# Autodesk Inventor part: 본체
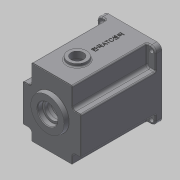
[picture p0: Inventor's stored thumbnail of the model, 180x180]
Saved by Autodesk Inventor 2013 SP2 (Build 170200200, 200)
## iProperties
Created: 2016-02
Part Number: 본체
Material: 일반
Document SubType Name: Modeling
Designer: mduedu
Density: 1 g/cm^3
Author: mduedu
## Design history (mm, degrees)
sketch "스케치1"
  geometry: L1 (-47, -47)-(47, -47); L2 (47, -47)-(47, 63); L3 (47, 63)-(-47, 63); L4 (-47, 63)-(-47, -47); 2 further points
  constraints: 8 end point, 2 parallel, 1 horizontal, 1 midpoint, 1 perpendicular, 1 vertical alignment
  dimensions: "d0" = 94 distance of L2.end L3.end; "d155" = 110 distance of L1.end L2.end; "d156" = 47 distance from line of L1 point (0, 0)
extrude "돌출1" new body sketch "스케치1" distance "d2" = 130; taper "d3" = 0 deg
sketch "스케치3"
  geometry: C1 r 40 at (0, 0); 1 further point
  constraints: 1 centre point, 1 coincident
  dimensions: "d9" = 80 diameter of C1
extrude "돌출3" cut sketch "스케치3" distance "d11" = 121; taper "d12" = 0 deg
sketch "스케치4"
  geometry: C1 r 21 at (0, 11); 1 further point
  constraints: 1 centre point, 1 vertical alignment
  dimensions: "d13" = 21 radius of C1; "d15" = 11 distance of point (0, 0) C1.centre
extrude "돌출4" join sketch "스케치4" distance "d16" = 7; taper "d17" = 0 deg
sketch "스케치5"
  geometry: C1 r 15 at (0, -20); 1 further point
  constraints: 1 centre point, 1 vertical alignment
  dimensions: "d18" = 15 radius of C1; "d20" = 20 distance of point (0, 0) C1.centre
extrude "돌출5" join sketch "스케치5" distance "d21" = 7; taper "d22" = 0 deg
sketch "스케치6"
  geometry: C1 r 28 at (0, 11); A1 r 21 centre (0, 11) between (8.978, -7.984) and (-8.978, -7.984) reference; 1 further point
  constraints: 1 centre point, 1 coincident
  dimensions: "d23" = 56 diameter of C1
extrude "돌출6" join sketch "스케치6" distance "d25" = 7; taper "d26" = -10 deg
hole "구멍1" diameter "d29" = 35; stored, may be unused: countersink angle "d33" = 90 deg, drill point angle "d35" = 0 deg; dims "d27" = 10, "d28" = 10, "d30" = 6, "d31" = 4, "d32" = 2, "d34" = 10
hole "구멍2" diameter "d38" = 22; stored, may be unused: countersink angle "d42" = 90 deg, drill point angle "d44" = 0 deg; dims "d36" = 10, "d37" = 10, "d39" = 6, "d40" = 4, "d41" = 2, "d43" = 7
hole "구멍3" diameter "d47" = 19; stored, may be unused: countersink angle "d51" = 90 deg, drill point angle "d53" = 0 deg; dims "d45" = 10, "d46" = 10, "d48" = 6, "d49" = 4, "d50" = 2, "d52" = 1
hole "구멍4" diameter "d56" = 32; stored, may be unused: countersink angle "d60" = 90 deg, drill point angle "d62" = 0 deg; dims "d54" = 10, "d55" = 10, "d57" = 6, "d58" = 4, "d59" = 2, "d61" = 8
hole "구멍5" diameter "d65" = 25; stored, may be unused: countersink angle "d69" = 90 deg, drill point angle "d71" = 0 deg; dims "d63" = 10, "d64" = 10, "d66" = 6, "d67" = 4, "d68" = 2, "d70" = 8
fillet "모깎기2" dims "d73" = 0.3
fillet "모깎기3" dims "d74" = 2
chamfer "모따기1" distance "d75" = 1; stored, may be unused: second distance "d76" = 2, angle "d77" = 45 deg
fillet "모깎기4" dims "d78" = 3
sketch "스케치16"
  geometry: L1 (-23, 32.726)-(23, 32.726); L2 (23, 32.726)-(23, 53); L3 (23, 53)-(-23, 53); L4 (-23, 53)-(-23, 32.726); L5 (-47, 63)-(47, 63) reference; 3 further points
  constraints: 8 end point, 2 parallel, 1 horizontal, 1 midpoint, 1 perpendicular, 1 vertical alignment, 2 other
  dimensions: "d160" = 46 distance of L2.end L3.end; "d163" = 10 distance between parallel lines of L3 L5
extrude "돌출15" cut sketch "스케치16" stored distance "d164" = 10; taper "d165" = 0 deg
fillet "모깎기5" dims "d79" = 2
fillet "모깎기15" dims "d166" = 5
sketch "스케치7"
  geometry: L1 (-23, 48)-(-23, 35.228) reference; L2 (23, 35.228)-(23, 48) reference; L3 (18, 53)-(-18, 53) reference; L4 (47, 63)-(47, -47) reference; L5 (47, -47)-(-47, -47) reference; L6 (-47, -47)-(-47, 63) reference; L7 (-47, 63)-(47, 63) reference; L8 (-26, 48)-(-26, 35.228); L9 (26, 35.228)-(26, 48); L10 (18, 56)-(-18, 56); C1 r 43 at (0, 0); A1 r 5 centre (-18, 48) between (-18, 53) and (-23, 48) reference; A2 r 5 centre (-28, 35.228) between (-24.889, 31.314) and (-23, 35.228) reference; A3 r 40 centre (0, 0) between (-24.889, 31.314) and (24.889, 31.314) reference; A4 r 5 centre (28, 35.228) between (23, 35.228) and (24.889, 31.314) reference; A5 r 5 centre (18, 48) between (23, 48) and (18, 53) reference; A6 r 8 centre (-18, 48) between (-18, 56) and (-26, 48); A7 r 2 centre (-28, 35.228) between (-26.756, 33.662) and (-26, 35.228); A8 r 43 centre (0, 0) between (-26.756, 33.662) and (26.756, 33.662); A9 r 2 centre (28, 35.228) between (26, 35.228) and (26.756, 33.662); A10 r 8 centre (18, 48) between (26, 48) and (18, 56); 1 further point
  constraints: 10 point on circle, 6 centre point, 6 end point, 1 coincident, 7 other
  dimensions: "d80" = 86 diameter of C1; "d167" = 3 distance between parallel lines of L3 L10
extrude "돌출7" cut sketch "스케치7" distance "d83" = 9; taper "d84" = 0 deg
sketch "스케치8" dims "d168" = 36
  geometry: L1 (-36, 4)-(-39.799, 4); L2 (-36, -4)-(-39.799, -4); A1 r 4 centre (-36, 0) between (-36, 4) and (-36, -4); A2 r 40 centre (0, 0) between (-24.889, 31.314) and (24.889, 31.314) reference; A3 r 40 centre (0, 0) between (-39.799, 4) and (-39.799, -4); 2 further points
  constraints: 5 point on circle, 4 end point, 2 centre point, 2 coincident, 2 horizontal alignment, 2 tangent, 1 horizontal, 1 parallel, 2 other
  dimensions: "d169" = 4 radius of A1
extrude "돌출9" join sketch "스케치8" stored distance "d89" = 9; taper "d90" = 0 deg
fillet "모깎기6" dims "d91" = 3.5
sketch "스케치9"
  geometry: L1 (47, 63)-(-47, 63) reference; L2 (47, -47)-(47, 63) reference; L3 (47, 63)-(33, 63); L4 (33, 63)-(33, 30); L5 (33, 30)-(47, 30); L6 (47, 30)-(47, 63); 2 further points
  constraints: 8 end point, 2 parallel, 1 horizontal, 1 perpendicular
  dimensions: "d95" = 33 distance from line of L4 point (0, 0); "d96" = 30 distance from line of L5 point (0, 0)
extrude "돌출10" cut sketch "스케치9" distance "d97" = 120; taper "d98" = 0 deg
sketch "스케치11"
  geometry: L1 (-40, -40)-(40, -40); L2 (40, -40)-(40, 56); L3 (40, 56)-(-40, 56); L4 (-40, 56)-(-40, -40); L5 (-47, -47)-(47, -47) reference; L6 (47, 63)-(-47, 63) reference; L7 (-47, 63)-(-47, -47) reference; C1 r 3.5 at (-40, 56); C2 r 3.5 at (40, 56); C3 r 3.5 at (40, -40); C4 r 3.5 at (-40, -40); 1 further point
  constraints: 8 end point, 4 centre point, 4 coincident, 3 equal radius, 2 parallel, 1 horizontal, 1 perpendicular
  dimensions: "d109" = 80 distance of L2.end L3.end; "d112" = 7 diameter of C1; "d157" = 7 distance from line of L1.start L5; "d158" = 7 distance between parallel lines of L6 L3; "d159" = 7 distance from line of L7 L3.end
extrude "돌출12" cut sketch "스케치11" stored distance "d113" = 63; taper "d114" = 0 deg
fillet "모깎기7" dims "d115" = 8
fillet "모깎기8" dims "d116" = 5
fillet "모깎기11" dims "d119" = 2
fillet "모깎기12" dims "d120" = 2
fillet "모깎기13" dims "d121" = 2
sketch "스케치12"
  geometry: 3 further points
  constraints: 2 horizontal alignment
hole "구멍6" sketch "스케치12" at (36, 0), (-36, 0) diameter "d122" = 3.242; stored, may be unused: countersink angle "d126" = 90 deg, drill point angle "d128" = 120 deg; dims "d123" = 7, "d124" = 4, "d125" = 2, "d127" = 9
sketch "스케치13"
  geometry: L1 (-33, 35)-(-33, 61) reference; L2 (-31, 63)-(31, 63) reference; L3 (33, 61)-(33, 35) reference; L4 (33, -35)-(33, -45) reference; L5 (31, -47)-(-31, -47) reference; L6 (-33, -45)-(-33, -35) reference; L7 (38, 30)-(45, 30) reference; L8 (47, 28)-(47, -28) reference; L9 (45, -30)-(38, -30) reference; L10 (-38, -30)-(-45, -30) reference; L11 (-47, -28)-(-47, 28) reference; L12 (-45, 30)-(-38, 30) reference; L13 (31, 62)-(-31, 62); L14 (-32, 61)-(-32, 35); L15 (-38, 29)-(-45, 29); L16 (-46, 28)-(-46, -28); L17 (-45, -29)-(-38, -29); L18 (-32, -35)-(-32, -45); L19 (-31, -46)-(31, -46); L20 (32, -45)-(32, -35); L21 (38, -29)-(45, -29); L22 (46, -28)-(46, 28); L23 (45, 29)-(38, 29); L24 (32, 35)-(32, 61); L25 (38, 30)-(45, 30) reference; L26 (47, 28)-(47, -28) reference; L27 (45, -30)-(38, -30) reference; L28 (33, -35)-(33, -45) reference; L29 (31, -47)-(-31, -47) reference; L30 (-33, -45)-(-33, -35) reference; L31 (-38, -30)-(-45, -30) reference; L32 (-47, -28)-(-47, 28) reference; L33 (-45, 30)-(-38, 30) reference; L34 (-33, 35)-(-33, 61) reference; L35 (33, 61)-(33, 35) reference; L36 (-31, 63)-(31, 63) reference; C1 r 16 at (0, 11) reference; C2 r 28 at (0, 11) reference; C3 r 16 at (0, 11) reference; C4 r 28 at (0, 11) reference; A1 r 5 centre (-38, 35) between (-38, 30) and (-33, 35) reference; A2 r 2 centre (-31, 61) between (-31, 63) and (-33, 61) reference; A3 r 2 centre (31, 61) between (33, 61) and (31, 63) reference; A4 r 5 centre (38, 35) between (33, 35) and (38, 30) reference; A5 r 5 centre (38, -35) between (38, -30) and (33, -35) reference; A6 r 2 centre (31, -45) between (31, -47) and (33, -45) reference; A7 r 2 centre (-31, -45) between (-33, -45) and (-31, -47) reference; A8 r 5 centre (-38, -35) between (-33, -35) and (-38, -30) reference; A9 r 2 centre (45, 28) between (47, 28) and (45, 30) reference; A10 r 2 centre (45, -28) between (45, -30) and (47, -28) reference; A11 r 2 centre (-45, -28) between (-47, -28) and (-45, -30) reference; A12 r 2 centre (-45, 28) between (-45, 30) and (-47, 28) reference; A13 r 1 centre (-31, 61) between (-31, 62) and (-32, 61); A14 r 6 centre (-38, 35) between (-38, 29) and (-32, 35); A15 r 1 centre (-45, 28) between (-45, 29) and (-46, 28); A16 r 1 centre (-45, -28) between (-46, -28) and (-45, -29); A17 r 6 centre (-38, -35) between (-32, -35) and (-38, -29); A18 r 1 centre (-31, -45) between (-32, -45) and (-31, -46); A19 r 1 centre (31, -45) between (31, -46) and (32, -45); A20 r 6 centre (38, -35) between (38, -29) and (32, -35); A21 r 1 centre (45, -28) between (45, -29) and (46, -28); A22 r 1 centre (45, 28) between (46, 28) and (45, 29); A23 r 6 centre (38, 35) between (32, 35) and (38, 29); A24 r 1 centre (31, 61) between (32, 61) and (31, 62); A25 r 5 centre (38, 35) between (33, 35) and (38, 30) reference; A26 r 2 centre (45, 28) between (47, 28) and (45, 30) reference; A27 r 2 centre (45, -28) between (45, -30) and (47, -28) reference; A28 r 5 centre (38, -35) between (38, -30) and (33, -35) reference; A29 r 2 centre (31, -45) between (31, -47) and (33, -45) reference; A30 r 2 centre (-31, -45) between (-33, -45) and (-31, -47) reference; A31 r 5 centre (-38, -35) between (-33, -35) and (-38, -30) reference; A32 r 2 centre (-45, -28) between (-47, -28) and (-45, -30) reference; A33 r 2 centre (-45, 28) between (-45, 30) and (-47, 28) reference; A34 r 5 centre (-38, 35) between (-38, 30) and (-33, 35) reference; A35 r 2 centre (-31, 61) between (-31, 63) and (-33, 61) reference; A36 r 2 centre (31, 61) between (33, 61) and (31, 63) reference
  constraints: 24 end point, 24 point on circle, 12 centre point, 23 other
  dimensions: "d154" = 1 distance between parallel lines of L13 L2
extrude "돌출13" cut sketch "스케치13" distance "d130" = 1; taper "d131" = 0 deg
fillet "모깎기14" dims "d147" = 0.3
sketch "스케치15"
  geometry: L1 (78, 0)-(0, 0) reference; 3 further points
  constraints: 1 midpoint, 1 vertical alignment, 1 other
  dimensions: "d148" = 40 distance of point (39, -40) point (39, 0)
feature "엠보싱1" sketch "스케치15" dims "d22" = 0, "d149" = 0.5, "d150" = 0
chamfer "모따기4" distance "d151" = 1; stored, may be unused: second distance "d152" = 2, angle "d153" = 45 deg
sketch "스케치17"
  geometry: L1 (39.004, -17.213)-(39.004, -18.809) reference; L2 (39.004, -18.809)-(38.548, -18.809) reference; L3 (38.548, -18.809)-(38.548, -17.213) reference; L4 (38.548, -17.213)-(35.455, -17.213) reference; L5 (35.455, -17.213)-(35.455, -16.822) reference; L6 (35.772, -16.659)-(42.578, -16.659) reference; L7 (42.578, -16.659)-(42.578, -17.213) reference; L8 (42.578, -17.213)-(39.004, -17.213) reference; L9 (38.223, -56.73)-(38.695, -56.73) reference; L10 (38.695, -56.73)-(38.695, -58.073) reference; L11 (38.695, -58.073)-(40.787, -58.073) reference; L12 (40.787, -58.073)-(40.787, -58.643) reference; L13 (40.787, -58.643)-(35.398, -58.643) reference; L14 (35.398, -58.643)-(35.398, -58.277) reference; L15 (35.715, -58.073)-(38.223, -58.073) reference; L16 (38.223, -58.073)-(38.223, -56.73) reference; L17 (41.927, -57.813)-(42.383, -57.813) reference; L18 (42.383, -57.813)-(42.383, -63.031) reference; L19 (42.383, -63.031)-(40.429, -63.031) reference; L20 (40.429, -63.031)-(40.429, -62.608) reference; L21 (40.689, -62.478)-(41.927, -62.478) reference; L22 (41.927, -62.478)-(41.927, -57.813) reference; L23 (36.09, -60.849)-(36.09, -62.624) reference; L24 (36.09, -62.624)-(35.666, -62.624) reference; L25 (35.666, -62.624)-(35.666, -60.849) reference; L26 (35.666, -60.849)-(36.09, -60.849) reference; L27 (37.058, -64.057)-(36.635, -64.057) reference; L28 (36.635, -64.057)-(36.635, -59.539) reference; L29 (36.635, -59.539)-(37.058, -59.539) reference; L30 (37.058, -59.539)-(37.058, -64.057) reference; L31 (42.138, -43.501)-(40.307, -44.168) reference; L32 (40.307, -44.168)-(40.307, -46.871) reference; L33 (40.307, -46.871)-(42.138, -47.555) reference; L34 (42.138, -47.555)-(42.138, -48.133) reference; L35 (42.138, -48.133)-(36.138, -45.853) reference; L36 (36.138, -45.853)-(36.138, -45.202) reference; L37 (36.138, -45.202)-(42.138, -42.923) reference; L38 (42.138, -42.923)-(42.138, -43.501) reference; L39 (36.725, -45.536)-(39.81, -46.684) reference; L40 (39.81, -46.684)-(39.81, -44.364) reference; L41 (39.81, -44.364)-(36.725, -45.536) reference; L42 (40.022, -52.114)-(40.022, -49.94) reference; L43 (40.022, -49.94)-(42.57, -49.94) reference; L44 (42.57, -49.94)-(42.57, -50.494) reference; L45 (42.57, -50.494)-(40.469, -50.494) reference; L46 (40.469, -50.494)-(40.469, -55.094) reference; L47 (40.469, -55.094)-(40.022, -55.094) reference; L48 (40.022, -55.094)-(40.022, -52.659) reference; L49 (40.022, -52.659)-(38.556, -52.659) reference; L50 (38.556, -52.659)-(38.556, -55.973) reference; L51 (38.556, -55.973)-(38.109, -55.973) reference; L52 (38.109, -55.973)-(38.109, -50.73) reference; L53 (36.106, -50.388)-(36.106, -54.955) reference; L54 (36.106, -54.955)-(35.65, -54.955) reference; L55 (35.65, -54.955)-(35.65, -49.81) reference; L56 (38.109, -50.136)-(38.109, -48.768) reference; L57 (38.109, -48.768)-(38.556, -48.768) reference; L58 (38.556, -48.768)-(38.556, -52.114) reference; L59 (38.556, -52.114)-(40.022, -52.114) reference; L60 (36.138, -38.168)-(36.635, -38.168) reference; L61 (36.635, -38.168)-(36.635, -40.041) reference; L62 (36.635, -40.041)-(42.138, -40.041) reference; L63 (42.138, -40.041)-(42.138, -40.586) reference; L64 (42.138, -40.586)-(36.635, -40.586) reference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; C1 r 10 at (39, -89); A1 r 4 centre (4, -12) between (8, -12) and (4, -8) reference; A2 r 4 centre (74, -12) between (74, -8) and (70, -12) reference; 61 further points
  constraints: 2 end point, 1 centre point, 1 midpoint, 1 point on line, 76 other
  dimensions: "d170" = 20 diameter of C1; "d171" = 41 distance from line of C1.centre L110
extrude "돌출16" cut sketch "스케치17" stored distance "d172" = 10; taper "d173" = 0 deg
sketch "스케치18"
  geometry: C1 r 10 at (39, -89) reference; C2 r 15 at (39, -89); 1 further point
  constraints: 1 centre point, 1 coincident
  dimensions: "d174" = 30 diameter of C2
extrude "돌출17" join sketch "스케치18" distance "d175" = 5; taper "d176" = 0 deg
fillet "모깎기16" dims "d177" = 2
sketch "스케치19"
  geometry: C1 r 10 at (18, 80) reference; C2 r 15 at (18, 80); 1 further point
  constraints: 1 centre point, 1 coincident
  dimensions: "d178" = 30 diameter of C2
extrude "돌출18" cut sketch "스케치19" distance "d181" = 5; taper "d182" = 0 deg
chamfer "모따기5" distance "d183" = 0.5; stored, may be unused: second distance "d184" = 2, angle "d185" = 45 deg
node "솔리드1"
pattern_circular "원형 패턴1" dims angle "d93" = 360 deg
mirror "대칭1"
mirror "대칭2"
node "절단 모서리 투영1"
node "절단 모서리 투영2"
node "절단 모서리 투영3"
node "절단 모서리 투영4"
